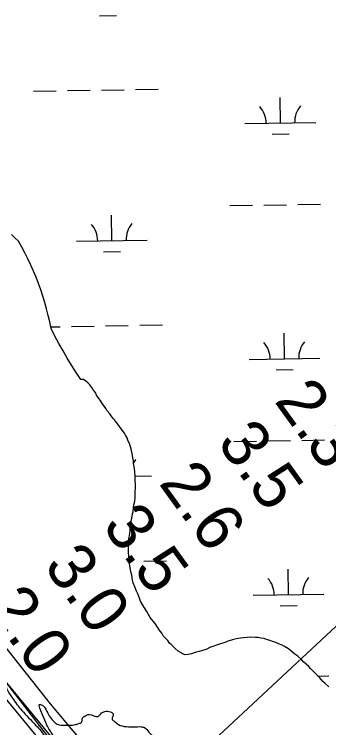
# Model space of a CAD drawing. Extents: x 3887375 to 3925618, y 296674 to 322633.
# Drawn here: x 3903543 to 3903987, y 304360 to 305367 of the extents above; entities that cross this region are included whole.
import ezdxf

# ---------------------------------------------------------------- set-up
doc = ezdxf.new("R2010")
doc.units = 0
for name, color, linetype in [('V-RIVR-EDGE', 7, 'Continuous'), ('V-RIVR-JETY', 7, 'Continuous'), ('V-RIVR-RANG', 7, 'Continuous'), ('V-RRAP-FSHR', 7, 'Continuous'), ('V-TOPO-DPTH', 7, 'Continuous'), ('V-TOPO-WATR', 7, 'Continuous'), ('V-WETL-SWMP', 7, 'Continuous')]:
    doc.layers.add(name, color=color, linetype=linetype)

msp = doc.modelspace()

# ---------------------------------------------------------------- linework, layer by layer
at = {"layer": 'V-RIVR-EDGE'}
msp.add_spline([(3903076.8, 304976.4), (3903099.6, 304951.7), (3903133.5, 304913.7), (3903157.3, 304882.8), (3903201.1, 304824.5), (3903232.9, 304785.1), (3903255.5, 304757.1), (3903311.1, 304686.2), (3903339, 304653.5), (3903361.5, 304623.5), (3903379.1, 304600.2), (3903404.6, 304571.6), (3903422.2, 304547.9), (3903438.8, 304529.2), (3903459, 304505.6), (3903478.9, 304488.2), (3903495.2, 304473.9), (3903506.8, 304465.6), (3903514.4, 304455.6), (3903517.7, 304442.9), (3903525, 304435.9), (3903528, 304430.3), (3903533.3, 304414.6), (3903540.6, 304402.3), (3903553.8, 304385), (3903573.4, 304364.3), (3903587.6, 304346.3), (3903597.9, 304330), (3903605.9, 304324), (3903619.5, 304318), (3903629.1, 304317.6), (3903632.8, 304318.3), (3903633.1, 304320.9), (3903633.5, 304324.3), (3903630.5, 304325.9), (3903622.8, 304326.6), (3903615.5, 304329.9), (3903606.2, 304338.3), (3903597.6, 304350.3), (3903589.3, 304364.3), (3903583.7, 304377.9), (3903578.4, 304391.9), (3903578.4, 304392.9), (3903580.1, 304393.2), (3903589.4, 304383.2), (3903599.7, 304368.6), (3903605.3, 304364.9), (3903612.6, 304364.2), (3903629.3, 304364.8), (3903634.2, 304366.5), (3903638.2, 304368.1), (3903639.3, 304373.8), (3903643.6, 304377.4), (3903648.9, 304379.1), (3903661.2, 304376.4), (3903666.5, 304381.4), (3903670.9, 304383.3), (3903678.8, 304383), (3903682.5, 304380.3), (3903681.5, 304372.3), (3903684.5, 304369.3), (3903690.1, 304365), (3903701.4, 304362), (3903712.4, 304361.6), (3903722, 304361.9), (3903727, 304360.6), (3903733, 304354.3), (3903743.6, 304342.3), (3903751.2, 304323), (3903759.5, 304308.6), (3903773.7, 304295.6), (3903789, 304280.3), (3903789.3, 304273.7), (3903788.3, 304266.7), (3903788.6, 304258), (3903792.2, 304248), (3903804.2, 304230.1), (3903817.7, 304208.1), (3903825.4, 304197.7), (3903828.4, 304195.1), (3903832.7, 304194.4), (3903838, 304199.4), (3903840, 304194.7), (3903840.6, 304188.7), (3903836.6, 304174.4), (3903836.3, 304162.1), (3903833.9, 304151.2), (3903823.2, 304132.6), (3903817.9, 304125.6), (3903807.2, 304122.3), (3903805.2, 304120.6), (3903803.2, 304116), (3903802.8, 304100.7), (3903801.2, 304098.7), (3903799.5, 304102), (3903789.9, 304117.7), (3903782.3, 304126.7), (3903774.7, 304132), (3903768, 304139), (3903763.1, 304152.3), (3903763.1, 304158), (3903770.8, 304167)], degree=3, dxfattribs=at)
at = {"layer": 'V-RIVR-JETY'}
for points in [[(3903654.5, 304276.3), (3903472.4, 304496.3)], [(3903510.2, 304426.2), (3903608.3, 304307.1)]]:
    msp.add_lwpolyline(points, dxfattribs=at)
at = {"layer": 'V-RIVR-RANG'}
msp.add_line((3904056.2, 304558.7), (3903544.1, 304081.5), dxfattribs=at)
at = {"layer": 'V-RRAP-FSHR'}
msp.add_lwpolyline([(3903045.7, 305153), (3903000.5, 305110.1), (3902999.7, 305092.9), (3903080.3, 305002.7), (3903213.4, 304858.1), (3903256.6, 304808.5), (3903352.6, 304698.4), (3903593.7, 304394.4), (3903689.6, 304280), (3903700.5, 304276.3), (3903747.8, 304312.8)], dxfattribs=at)
at = {"layer": 'V-TOPO-DPTH'}
msp.add_lwpolyline([(3903859.2, 304002.2), (3903567.5, 304378.2), (3903545.4, 304406.9), (3903523.4, 304435.6), (3903501.7, 304464.5), (3903480.1, 304493.5), (3903409.1, 304589.4), (3903352.1, 304666.3), (3903295, 304743.2), (3903237.7, 304820), (3903180.4, 304896.8), (3903098.9, 305005.9), (3903077.9, 305033.5), (3903056.7, 305060.9), (3903035.1, 305088.1), (3903013.2, 305115), (3902805.9, 305366.7)], dxfattribs=at)
at = {"layer": 'V-TOPO-WATR'}
msp.add_lwpolyline([(3903859.2, 304002.2), (3903567.5, 304378.2), (3903545.4, 304406.9), (3903523.4, 304435.6), (3903501.7, 304464.5), (3903480.1, 304493.5), (3903409.1, 304589.4), (3903352.1, 304666.3), (3903295, 304743.2), (3903237.7, 304820), (3903180.4, 304896.8), (3903098.9, 305005.9), (3903077.9, 305033.5), (3903056.7, 305060.9), (3903035.1, 305088.1), (3903013.2, 305115), (3902805.9, 305366.7)], dxfattribs=at)
at = {"layer": 'V-WETL-SWMP'}
for p, q in [((3903663.5, 305364.5), (3903687.5, 305364.9)), ((3903570.4, 305258.2), (3903602.4, 305258.8)), ((3903618.4, 305259), (3903650.4, 305259.6)), ((3903666.4, 305259.9), (3903698.4, 305260.4)), ((3903714.4, 305260.7), (3903746.4, 305261.2)), ((3903918.6, 305213.4), (3903918, 305249.4)), ((3903868.6, 305212.6), (3903968.6, 305214.3)), ((3903906.8, 305197.8), (3903930.8, 305198.2)), ((3903847.2, 305096.8), (3903879.1, 305097.3)), ((3903895.1, 305097.6), (3903927.1, 305098.1)), ((3903943.1, 305098.4), (3903975.1, 305099)), ((3903680.9, 305047.5), (3903680.3, 305083.5)), ((3903544.3, 305051.5), (3903539.2, 305056.2)), ((3903549.2, 305046.6), (3903544.3, 305051.5)), ((3903553.8, 305038.4), (3903549.2, 305046.6)), ((3903630.9, 305046.6), (3903730.9, 305048.3)), ((3903558.3, 305030.1), (3903553.8, 305038.4)), ((3903562.5, 305021.7), (3903558.3, 305030.1)), ((3903669.2, 305031.8), (3903693.2, 305032.2)), ((3903566.6, 305013.1), (3903562.5, 305021.7)), ((3903570.4, 305004.5), (3903566.6, 305013.1)), ((3903574, 304995.8), (3903570.4, 305004.5)), ((3903577.4, 304987), (3903574, 304995.8)), ((3903580.6, 304978.2), (3903577.4, 304987)), ((3903583.6, 304969.2), (3903580.6, 304978.2)), ((3903586.4, 304960.2), (3903583.6, 304969.2)), ((3903588.9, 304951.1), (3903586.4, 304960.2)), ((3903591.3, 304942), (3903588.9, 304951.1)), ((3903593.4, 304932.8), (3903591.3, 304942)), ((3903595.2, 304923.6), (3903593.4, 304932.8)), ((3903594.8, 304925.9), (3903608.1, 304926.1)), ((3903600.6, 304912.9), (3903595.2, 304923.6)), ((3903624.1, 304926.4), (3903656.1, 304927)), ((3903672.1, 304927.2), (3903704.1, 304927.8)), ((3903720.1, 304928.1), (3903752.1, 304928.6)), ((3903606.2, 304902.4), (3903600.6, 304912.9)), ((3903924.3, 304880.8), (3903923.7, 304916.8)), ((3903612, 304892), (3903606.2, 304902.4)), ((3903618, 304881.8), (3903612, 304892)), ((3903624.2, 304871.6), (3903618, 304881.8)), ((3903874.3, 304879.9), (3903974.3, 304881.7)), ((3903630.6, 304861.6), (3903624.2, 304871.6)), ((3903637.2, 304851.7), (3903630.6, 304861.6)), ((3903912.5, 304865.2), (3903936.5, 304865.6)), ((3903640.7, 304851.4), (3903637.2, 304851.7)), ((3903644.3, 304849.2), (3903640.7, 304851.4)), ((3903647.4, 304846.6), (3903644.3, 304849.2)), ((3903650, 304844), (3903647.4, 304846.6)), ((3903652.7, 304840.1), (3903650, 304844)), ((3903654.5, 304837), (3903652.7, 304840.1)), ((3903657.6, 304833.1), (3903654.5, 304837)), ((3903659.4, 304829.7), (3903657.6, 304833.1)), ((3903661.6, 304826.2), (3903659.4, 304829.7)), ((3903664.3, 304822.7), (3903661.6, 304826.2)), ((3903667.8, 304817.5), (3903664.3, 304822.7)), ((3903672.3, 304810.5), (3903667.8, 304817.5)), ((3903674.5, 304807.5), (3903672.3, 304810.5)), ((3903678.1, 304803.1), (3903674.5, 304807.5)), ((3903679.8, 304800.5), (3903678.1, 304803.1)), ((3903682.5, 304796.6), (3903679.8, 304800.5)), ((3903684.7, 304794.5), (3903682.5, 304796.6)), ((3903687.4, 304791), (3903684.7, 304794.5)), ((3903689.2, 304788.4), (3903687.4, 304791)), ((3903694.1, 304781.9), (3903689.2, 304788.4)), ((3903698.5, 304775.8), (3903694.1, 304781.9)), ((3903700.3, 304773.2), (3903698.5, 304775.8)), ((3903702.5, 304769.2), (3903700.3, 304773.2)), ((3903703.5, 304766.2), (3903702.5, 304769.2)), ((3903706.1, 304760.1), (3903703.5, 304766.2)), ((3903852.9, 304764.1), (3903884.9, 304764.7)), ((3903900.9, 304765), (3903932.9, 304765.5)), ((3903948.8, 304765.8), (3903980.8, 304766.3)), ((3903707.1, 304756.6), (3903706.1, 304760.1)), ((3903708.4, 304751.3), (3903707.1, 304756.6)), ((3903709.4, 304747.4), (3903708.4, 304751.3)), ((3903710.3, 304741.3), (3903709.4, 304747.4)), ((3903711.2, 304736.9), (3903710.3, 304741.3)), ((3903711.3, 304733), (3903711.2, 304736.9)), ((3903712.7, 304726), (3903711.3, 304733)), ((3903713.2, 304720.7), (3903712.7, 304726)), ((3903713.7, 304715), (3903713.2, 304720.7)), ((3903713.6, 304715.3), (3903736.6, 304715.7)), ((3903713.7, 304710.2), (3903713.7, 304715)), ((3903714.2, 304703.2), (3903713.7, 304710.2)), ((3903714.3, 304698.8), (3903714.2, 304703.2)), ((3903713.9, 304693.1), (3903714.3, 304698.8)), ((3903713.9, 304689.2), (3903713.9, 304693.1)), ((3903713.2, 304680), (3903713.6, 304684.8)), ((3903713.6, 304684.8), (3903713.9, 304689.2)), ((3903710.7, 304665.1), (3903711.5, 304671.7)), ((3903711.5, 304671.7), (3903712.3, 304676.9)), ((3903712.3, 304676.9), (3903713.2, 304680)), ((3903709.1, 304655.9), (3903709.9, 304662)), ((3903709.9, 304662), (3903710.7, 304665.1)), ((3903707.8, 304649.7), (3903709.1, 304655.9)), ((3903706.6, 304639.2), (3903707, 304645.3)), ((3903707, 304645.3), (3903707.8, 304649.7)), ((3903705, 304626.5), (3903706.2, 304633.9)), ((3903706.2, 304633.9), (3903706.6, 304639.2)), ((3903704.2, 304619.9), (3903705, 304626.5)), ((3903704.3, 304615.1), (3903704.2, 304619.9)), ((3903704.3, 304608.9), (3903704.3, 304615.1)), ((3903704.9, 304601), (3903704.3, 304608.9)), ((3903705.8, 304591.9), (3903704.9, 304601)), ((3903705.5, 304595.1), (3903709.8, 304595.2)), ((3903707.7, 304580.5), (3903705.8, 304591.9)), ((3903725.8, 304595.4), (3903757.8, 304596)), ((3903709.1, 304575.7), (3903707.7, 304580.5)), ((3903930, 304548.2), (3903929.4, 304584.2)), ((3903710, 304568.7), (3903709.1, 304575.7)), ((3903711, 304564.8), (3903710, 304568.7)), ((3903713.2, 304559.1), (3903711, 304564.8)), ((3903715.5, 304553), (3903713.2, 304559.1)), ((3903717.3, 304549.1), (3903715.5, 304553)), ((3903720, 304543), (3903717.3, 304549.1)), ((3903721.3, 304539), (3903720, 304543)), ((3903880, 304547.3), (3903980, 304549)), ((3903724.4, 304533.4), (3903721.3, 304539)), ((3903726.7, 304529.4), (3903724.4, 304533.4)), ((3903730.2, 304524.2), (3903726.7, 304529.4)), ((3903918.3, 304532.5), (3903942.3, 304533)), ((3903735.1, 304516), (3903730.2, 304524.2)), ((3903739.1, 304510.8), (3903735.1, 304516)), ((3903741.8, 304507.3), (3903739.1, 304510.8)), ((3903745.4, 304502.1), (3903741.8, 304507.3)), ((3903747.6, 304498.6), (3903745.4, 304502.1)), ((3903751.2, 304493.8), (3903747.6, 304498.6)), ((3903753.4, 304490.3), (3903751.2, 304493.8)), ((3903756.9, 304486.4), (3903753.4, 304490.3)), ((3903759.6, 304483.4), (3903756.9, 304486.4)), ((3903762.3, 304479.9), (3903759.6, 304483.4)), ((3903764.5, 304477.7), (3903762.3, 304479.9)), ((3903837.2, 304479.9), (3903834.1, 304479)), ((3903841.6, 304481.2), (3903837.2, 304479.9)), ((3903844.6, 304482.6), (3903841.6, 304481.2)), ((3903849.4, 304483.9), (3903844.6, 304482.6)), ((3903852.5, 304484.9), (3903849.4, 304483.9)), ((3903856.8, 304485.8), (3903852.5, 304484.9)), ((3903862.1, 304486.7), (3903856.8, 304485.8)), ((3903866.5, 304487.2), (3903862.1, 304486.7)), ((3903871.7, 304487.7), (3903866.5, 304487.2)), ((3903877, 304488.2), (3903871.7, 304487.7)), ((3903883.5, 304487.8), (3903877, 304488.2)), ((3903887, 304487.9), (3903883.5, 304487.8)), ((3903891, 304487), (3903887, 304487.9)), ((3903895.8, 304486.2), (3903891, 304487)), ((3903898.9, 304484.9), (3903895.8, 304486.2)), ((3903903.7, 304483.7), (3903898.9, 304484.9)), ((3903909, 304481.5), (3903903.7, 304483.7)), ((3903912.1, 304480.7), (3903909, 304481.5)), ((3903916, 304479), (3903912.1, 304480.7)), ((3903767.1, 304475.1), (3903764.5, 304477.7)), ((3903770.2, 304472.1), (3903767.1, 304475.1)), ((3903774.2, 304468.6), (3903770.2, 304472.1)), ((3903807.5, 304469), (3903804, 304468.1)), ((3903811.9, 304470.4), (3903807.5, 304469)), ((3903814.9, 304471.3), (3903811.9, 304470.4)), ((3903818.9, 304473.5), (3903814.9, 304471.3)), ((3903823.2, 304474.9), (3903818.9, 304473.5)), ((3903828.5, 304476.7), (3903823.2, 304474.9)), ((3903834.1, 304479), (3903828.5, 304476.7)), ((3903920.9, 304476.9), (3903916, 304479)), ((3903924.4, 304475.1), (3903920.9, 304476.9)), ((3903930.1, 304471.7), (3903924.4, 304475.1)), ((3903933.2, 304468.7), (3903930.1, 304471.7)), ((3903777.8, 304466.5), (3903774.2, 304468.6)), ((3903780.4, 304464.8), (3903777.8, 304466.5)), ((3903784.4, 304463.5), (3903780.4, 304464.8)), ((3903788.7, 304463.6), (3903784.4, 304463.5)), ((3903793.1, 304464.9), (3903788.7, 304463.6)), ((3903798.3, 304466.7), (3903793.1, 304464.9)), ((3903804, 304468.1), (3903798.3, 304466.7)), ((3903939, 304464.3), (3903933.2, 304468.7)), ((3903943, 304461.3), (3903939, 304464.3)), ((3903948.3, 304456.6), (3903943, 304461.3)), ((3903951.8, 304453.1), (3903948.3, 304456.6)), ((3903958, 304447.5), (3903951.8, 304453.1)), ((3903961.6, 304443.6), (3903958, 304447.5)), ((3903966.9, 304437.9), (3903961.6, 304443.6)), ((3903970.9, 304434), (3903966.9, 304437.9)), ((3903974, 304431), (3903970.9, 304434)), ((3903971.5, 304433.4), (3903986.6, 304433.7)), ((3903978.4, 304425.8), (3903974, 304431)), ((3903981.5, 304422.8), (3903978.4, 304425.8)), ((3903986.8, 304418), (3903981.5, 304422.8))]:
    msp.add_line(p, q, dxfattribs=at)
for centre, start, end in [((3903863.3, 305213), 0.2115, 41.7552), ((3903973.8, 305214.9), 140.2115, 181.7552), ((3903625.7, 305047), 0.2115, 41.7552), ((3903736.1, 305048.9), 140.2115, 181.7552), ((3903869, 304880.3), 0.2115, 41.7552), ((3903979.5, 304882.2), 140.2115, 181.7552), ((3903741.8, 304716.3), 140.2115, 150.2093), ((3903874.7, 304547.7), 0.2115, 41.7552), ((3903985.2, 304549.6), 140.2115, 181.7552)]:
    msp.add_arc(centre, 35.2, start, end, dxfattribs=at)

# ---------------------------------------------------------------- texts
at = {"layer": 'V-RIVR-RANG'}
for s, p in [('2.3', (3903908.9, 304821.4)), ('3.5', (3903828, 304762.7)), ('2.6', (3903746, 304705.4)), ('3.5', (3903666.2, 304645.1)), ('3.0', (3903583.6, 304588.7)), ('2.0', (3903502.7, 304529.9))]:
    msp.add_text(s, height=67, rotation=305.8583, dxfattribs=at).set_placement(p)

doc.saveas('drawing.dxf')
